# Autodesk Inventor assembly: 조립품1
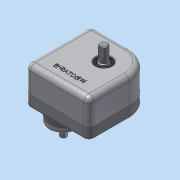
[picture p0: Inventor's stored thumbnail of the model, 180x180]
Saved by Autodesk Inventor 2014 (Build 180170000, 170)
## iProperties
Created: 2015-11
Part Number: 조립품1
Document SubType Name: Assembly
Designer: dgall
Author: dgall
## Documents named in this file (13)
- C:\Users\dgall\Desktop\2급\Inventor2급-윤지은\조립품1.iam
- C:\Users\dgall\Desktop\2급\Inventor2급-윤지은\본체.ipt
- C:\Users\dgall\Desktop\2급\Inventor2급-윤지은\앞커버.ipt
- C:\Users\dgall\Desktop\2급\Inventor2급-윤지은\베어링 6002.ipt
- C:\Users\dgall\Desktop\2급\Inventor2급-윤지은\축 커버.ipt
- C:\Users\dgall\Desktop\2급\Inventor2급-윤지은\베어링 6001.ipt
- C:\Users\dgall\Desktop\2급\Inventor2급-윤지은\로드 축.ipt
- C:\Users\dgall\Desktop\2급\Inventor2급-윤지은\편심 축.ipt
- C:\Users\dgall\Desktop\2급\Inventor2급-윤지은\로드.ipt
- C:\Users\dgall\Desktop\2급\Inventor2급-윤지은\오일실 15 x 25.ipt
- C:\Users\dgall\Desktop\2급\Inventor2급-윤지은\오일실 12 x 22.ipt
- C:\Users\dgall\Desktop\2급\Inventor2급-윤지은\M4 x 0.7.ipt
- C:\Users\dgall\Desktop\2급\Inventor2급-윤지은\M3 x 0.5.ipt
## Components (9 placed, 2 different names)
1. M4 x 0.7:1
2. M4 x 0.7:2
3. M4 x 0.7:3
4. M4 x 0.7:4
5. M4 x 0.7:5
6. M3 x 0.5:1
7. M3 x 0.5:2
8. M3 x 0.5:3
9. M3 x 0.5:4
